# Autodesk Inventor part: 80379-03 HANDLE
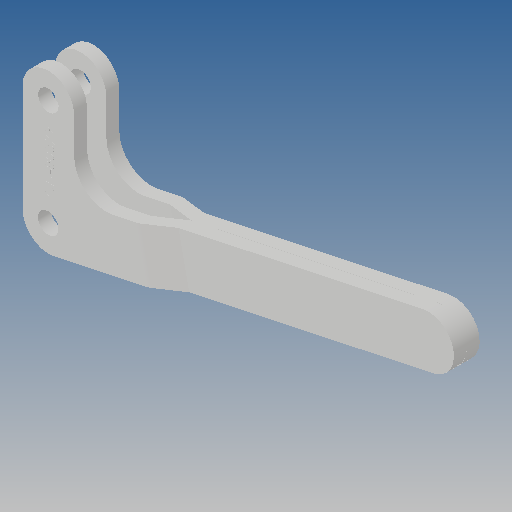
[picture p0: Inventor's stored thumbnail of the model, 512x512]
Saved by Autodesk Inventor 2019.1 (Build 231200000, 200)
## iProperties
Created: 2012-10
Part Number: 80379-03 HANDLE
Material: Ogólny
Document SubType Name: Modeling
Designer: CADENGINEERING4
Density: 1 g/cm^3
Appearance: Domyślna
Author: CADENGINEERING4
Revision Number: ÈÎºÎ
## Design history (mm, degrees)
feature "ÇÐ³ý-À­Éì4"
feature "ÇÐ³ý-À­Éì7"
node "Bryła1"
node "Bryła2"
